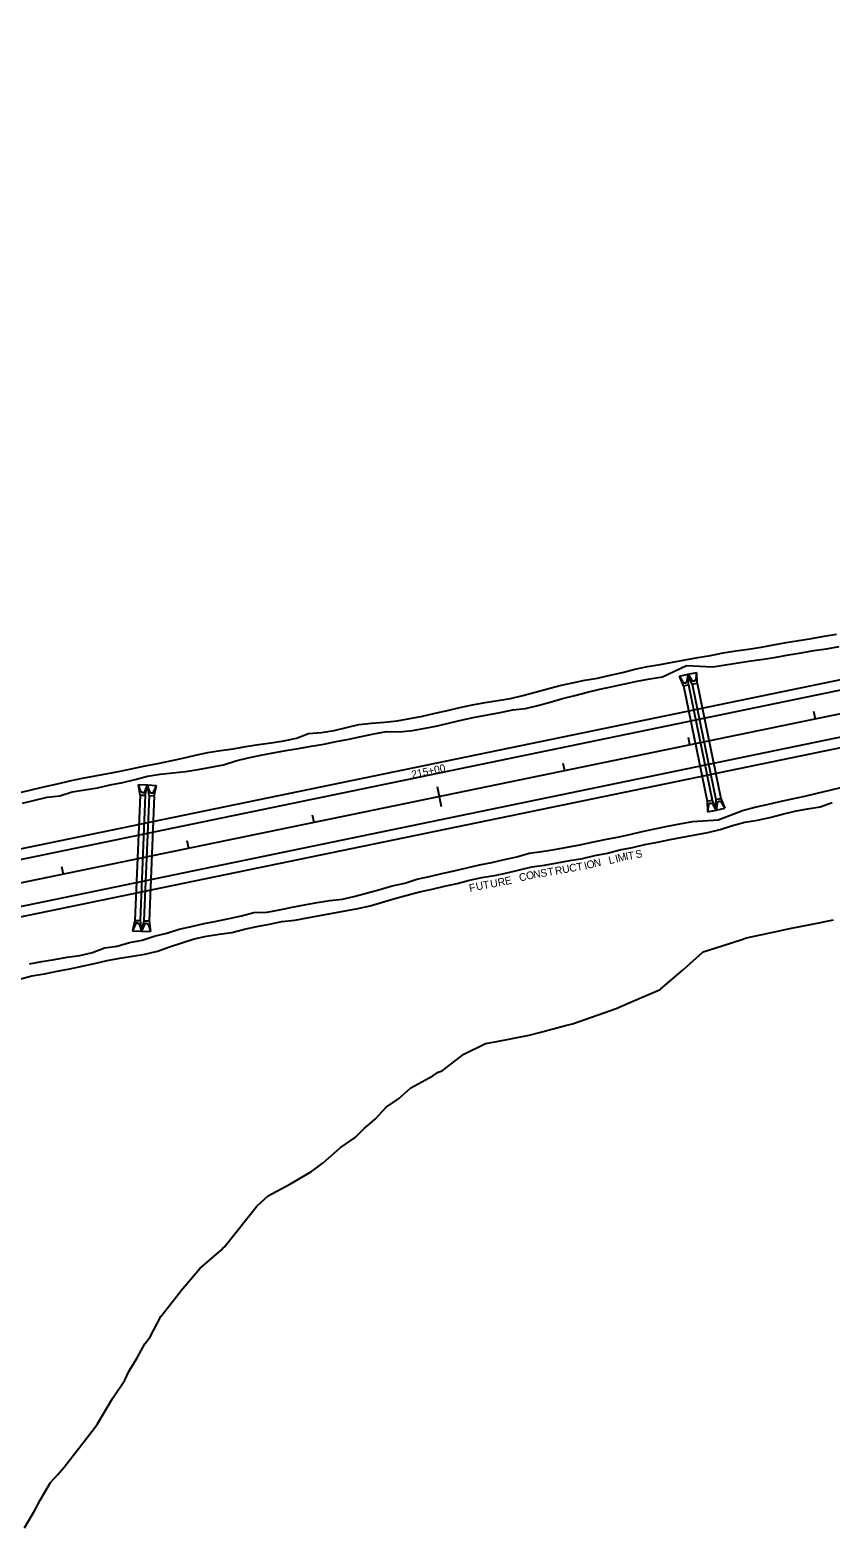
# Model space of a CAD drawing. Extents: x 979959 to 994833, y 1835619 to 1845316.
# Drawn here: x 986936 to 987562, y 1837739 to 1838917 of the extents above; entities that cross this region are included whole.
import ezdxf

# ---------------------------------------------------------------- set-up
doc = ezdxf.new("R2010")
doc.units = 0
for name, color, linetype in [('43', 7, 'Continuous'), ('Future 5 Lane Construction Limits', 7, 'Continuous'), ('R_Drainage', 7, 'Continuous'), ('R_Horz Alg', 7, 'Continuous'), ('R_Horz Alg Stationing', 7, 'Continuous'), ('R_Proposed Const Limits', 7, 'Continuous'), ('R_Proposed Road', 7, 'Continuous')]:
    doc.layers.add(name, color=color, linetype=linetype)

msp = doc.modelspace()

# ---------------------------------------------------------------- linework, layer by layer
at = {"layer": '43'}
msp.add_lwpolyline([(986932, 1837746.3), (986939.8, 1837759.8), (986944.4, 1837767.9), (986952.5, 1837781.7), (986958.2, 1837788.1), (986963, 1837793.8), (986986.5, 1837823.9), (986989.2, 1837827.8), (987000.9, 1837847.4), (987010.4, 1837861.8), (987013.6, 1837868.7), (987020.1, 1837879.2), (987020.5, 1837879.8), (987026.1, 1837890.1), (987030.2, 1837895.7), (987038.6, 1837911.6), (987052.9, 1837929.7), (987053.5, 1837930.7), (987054.5, 1837931.8), (987069, 1837949.2), (987086, 1837963.7), (987087.2, 1837965), (987088.5, 1837965.9), (987113.7, 1837997.7), (987122.5, 1838005.8), (987140, 1838015.2), (987156.5, 1838024.8), (987160.3, 1838027.8), (987165.6, 1838031.7), (987178.8, 1838043.3), (987190.4, 1838051.5), (987197.5, 1838058.6), (987206.2, 1838065.7), (987214.8, 1838075.3), (987224.5, 1838081.6), (987233.9, 1838090.2), (987251.2, 1838099.7), (987255.5, 1838102.6), (987258.4, 1838103.6), (987275.4, 1838116.6), (987292.4, 1838124.9), (987299.8, 1838126.3), (987326.4, 1838131.5), (987334.5, 1838133.6), (987355, 1838139), (987360.4, 1838140.2), (987380.5, 1838147.4), (987394.4, 1838152.2), (987405.2, 1838156.9), (987428.4, 1838166.8), (987428.8, 1838167.2), (987429.4, 1838167.6), (987447.2, 1838182.8), (987462.4, 1838196.7), (987478.1, 1838201.6), (987492, 1838206), (987496.3, 1838207.4), (987519.5, 1838212.4), (987530.3, 1838214.8), (987547.7, 1838218.2), (987564.3, 1838221.5)], dxfattribs=at)
at = {"layer": 'Future 5 Lane Construction Limits'}
for points in [[(986928.7, 1838321.1), (986938.4, 1838323.4), (986948.2, 1838325.7), (986957.9, 1838328), (986967.6, 1838330.3), (986977.4, 1838332.3), (986987.3, 1838334.2), (986997.1, 1838336), (987006.9, 1838337.8), (987016.7, 1838339.8), (987026.5, 1838341.9), (987036.3, 1838343.9), (987046.1, 1838345.9), (987055.9, 1838348), (987065.6, 1838350.2), (987075.4, 1838352.3), (987085.3, 1838353.9), (987095.2, 1838355.3), (987105.1, 1838357), (987115, 1838358.5), (987124.9, 1838360), (987134.8, 1838361.4), (987144.6, 1838363.6), (987154, 1838367.1), (987164.1, 1838368), (987174, 1838369.5), (987183.7, 1838371.9), (987193.4, 1838374.2), (987203.4, 1838375.3), (987213.4, 1838376.1), (987223.4, 1838377.1), (987233.3, 1838378.9), (987243.1, 1838380.9), (987252.9, 1838383), (987262.6, 1838385.3), (987272.3, 1838387.6), (987282.1, 1838389.6), (987292, 1838391.5), (987301.9, 1838393), (987311.8, 1838394.5), (987321.5, 1838397), (987331.2, 1838399.5), (987340.8, 1838402.2), (987350.5, 1838404.7), (987360.3, 1838406.8), (987370.1, 1838408.8), (987379.9, 1838410.5), (987389.7, 1838412.8), (987399.4, 1838414.9), (987409.1, 1838417.4), (987418.9, 1838419.5), (987428.8, 1838421.2), (987438.6, 1838422.9), (987448.5, 1838424.7), (987458.3, 1838426.5), (987468.1, 1838428.3), (987478, 1838430.3), (987487.9, 1838431.8), (987497.8, 1838433.1), (987507.7, 1838434.6), (987517.5, 1838436.6), (987527.4, 1838438.3), (987537.2, 1838439.9), (987547.1, 1838441.5), (987557, 1838443.3), (987566.8, 1838444.9)], [(986928.2, 1838175.2), (986937.9, 1838177.8), (986947.8, 1838179.3), (986957.5, 1838181.5), (986967.4, 1838183.3), (986977.2, 1838185.3), (986986.9, 1838187.4), (986996.6, 1838189.8), (987006.5, 1838191.7), (987016.4, 1838193.1), (987026.2, 1838194.8), (987036, 1838197.1), (987045.5, 1838200.4), (987055.1, 1838203.6), (987064.6, 1838206.8), (987074.4, 1838208.7), (987084.3, 1838210.3), (987094.2, 1838211.8), (987103.9, 1838214.2), (987113.7, 1838216.5), (987123.5, 1838218.2), (987133.3, 1838220.3), (987143.3, 1838221.4), (987153.1, 1838223.1), (987163, 1838224.9), (987172.8, 1838226.9), (987182.6, 1838228.7), (987192.5, 1838230.5), (987202.2, 1838232.6), (987211.9, 1838235.4), (987221.5, 1838238.3), (987231.1, 1838241), (987240.9, 1838243.4), (987250.6, 1838245.6), (987260.4, 1838247.8), (987270.1, 1838250.1), (987279.8, 1838252.5), (987289.6, 1838254.6), (987299.5, 1838256.2), (987309.2, 1838258.3), (987319, 1838260.7), (987328.7, 1838262.9), (987338.6, 1838264.4), (987348.5, 1838266.1), (987358.3, 1838268), (987368.2, 1838269.6), (987377.9, 1838272), (987387.7, 1838273.8), (987397.4, 1838276.4), (987407.3, 1838278.1), (987417, 1838280.4), (987426.8, 1838282.3), (987436.6, 1838284.4), (987446.4, 1838286.3), (987456.3, 1838288.1), (987466.1, 1838289.8), (987475.8, 1838292.2), (987485.4, 1838295.3), (987495.1, 1838297.9), (987505, 1838299.4), (987514.7, 1838301.7), (987524.4, 1838304.2), (987534.2, 1838306.4), (987544, 1838308.3), (987553.9, 1838310), (987563.4, 1838313.2)]]:
    msp.add_lwpolyline(points, dxfattribs=at)
at = {"layer": 'R_Drainage'}
for p, q in [((987443.9, 1838412.1), (987450.8, 1838413.5)), ((987447, 1838404.4), (987443.9, 1838412.1)), ((987446.6, 1838407.8), (987443.9, 1838412.1)), ((987450, 1838408.5), (987450.8, 1838413.5)), ((987450.8, 1838413.5), (987457.6, 1838415)), ((987451, 1838405.2), (987450.8, 1838413.5)), ((987453.9, 1838405.8), (987450.8, 1838413.5)), ((987453.5, 1838409.2), (987450.8, 1838413.5)), ((987456.9, 1838409.9), (987457.6, 1838415)), ((987457.8, 1838406.6), (987457.6, 1838415)), ((987447, 1838404.4), (987451, 1838405.2)), ((987447, 1838404.4), (987465.6, 1838314.3)), ((987451, 1838405.2), (987469.6, 1838315.1)), ((987453.9, 1838405.8), (987457.8, 1838406.6)), ((987453.9, 1838405.8), (987472.5, 1838315.7)), ((987457.8, 1838406.6), (987476.4, 1838316.5)), ((987021.2, 1838327.3), (987028.2, 1838327)), ((987022.4, 1838319.1), (987021.2, 1838327.3)), ((987022.8, 1838322.4), (987021.2, 1838327.3)), ((987026.3, 1838322.3), (987028.2, 1838327)), ((987026.4, 1838318.9), (987028.2, 1838327)), ((987028.2, 1838327), (987035.2, 1838326.7)), ((987029.4, 1838318.8), (987028.2, 1838327)), ((987029.8, 1838322.1), (987028.2, 1838327)), ((987033.2, 1838322), (987035.2, 1838326.7)), ((987033.4, 1838318.6), (987035.2, 1838326.7)), ((987022.4, 1838319.1), (987018.4, 1838221.2)), ((987022.4, 1838319.1), (987026.4, 1838318.9)), ((987026.4, 1838318.9), (987022.4, 1838221)), ((987029.4, 1838318.8), (987025.4, 1838220.9)), ((987029.4, 1838318.8), (987033.4, 1838318.6)), ((987033.4, 1838318.6), (987029.4, 1838220.7)), ((987465.6, 1838314.3), (987469.6, 1838315.1)), ((987465.6, 1838314.3), (987465.8, 1838306)), ((987469.6, 1838315.1), (987472.7, 1838307.4)), ((987472.5, 1838315.7), (987476.4, 1838316.5)), ((987472.5, 1838315.7), (987472.7, 1838307.4)), ((987476.4, 1838316.5), (987479.5, 1838308.9)), ((987466.6, 1838311.1), (987465.8, 1838306)), ((987465.8, 1838306), (987472.7, 1838307.4)), ((987470, 1838311.8), (987472.7, 1838307.4)), ((987473.5, 1838312.5), (987472.7, 1838307.4)), ((987472.7, 1838307.4), (987479.5, 1838308.9)), ((987476.8, 1838313.2), (987479.5, 1838308.9)), ((987018.4, 1838221.2), (987016.6, 1838213.1)), ((987018.4, 1838221.2), (987022.4, 1838221)), ((987022.4, 1838221), (987023.6, 1838212.8)), ((987025.4, 1838220.9), (987023.6, 1838212.8)), ((987025.4, 1838220.9), (987029.4, 1838220.7)), ((987029.4, 1838220.7), (987030.6, 1838212.5)), ((987018.5, 1838217.8), (987016.6, 1838213.1)), ((987016.6, 1838213.1), (987023.6, 1838212.8)), ((987022, 1838217.7), (987023.6, 1838212.8)), ((987025.5, 1838217.5), (987023.6, 1838212.8)), ((987023.6, 1838212.8), (987030.6, 1838212.5)), ((987029, 1838217.4), (987030.6, 1838212.5))]:
    msp.add_line(p, q, dxfattribs=at)
for centre, start, end in [((987448.2, 1838408.7), 211.983, 351.3459), ((987455.1, 1838410.2), 211.983, 351.3459), ((987024.6, 1838323), 197.983, 337.3459), ((987031.6, 1838322.7), 197.983, 337.3459), ((987475.3, 1838312.2), 31.9829, 171.3457), ((987468.4, 1838310.8), 31.9829, 171.3457), ((987020.2, 1838217.1), 17.9829, 157.3457), ((987027.2, 1838216.8), 17.9829, 157.3457)]:
    msp.add_arc(centre, 1.83, start, end, dxfattribs=at)
at = {"layer": 'R_Horz Alg'}
msp.add_line((984572.5, 1837764), (990033.8, 1838891.5), dxfattribs=at)
at = {"layer": 'R_Horz Alg Stationing'}
for points in [[(987548.7, 1838384.6), (987549.9, 1838378.7)], [(987450.7, 1838364.3), (987451.9, 1838358.5)], [(987352.8, 1838344.1), (987354, 1838338.3)], [(987254.5, 1838325.9), (987257.7, 1838310.2)], [(987156.9, 1838303.7), (987158.1, 1838297.8)], [(987059, 1838283.5), (987060.2, 1838277.6)], [(986961.1, 1838263.3), (986962.3, 1838257.4)]]:
    msp.add_lwpolyline(points, dxfattribs=at)
at = {"layer": 'R_Proposed Const Limits'}
for points in [[(986930.4, 1838312.7), (986940.2, 1838315), (986949.9, 1838317.5), (986959.8, 1838318.6), (986969.4, 1838321.7), (986979.3, 1838323.3), (986989.2, 1838324.8), (986999, 1838327), (987008.8, 1838328.8), (987018.5, 1838331.4), (987028.2, 1838333.9), (987038, 1838335.5), (987048, 1838336.6), (987058, 1838337.6), (987067.9, 1838339.1), (987077.8, 1838341), (987087.6, 1838342.8), (987097.2, 1838345.8), (987106.9, 1838348.3), (987116.7, 1838350.2), (987126.5, 1838352.1), (987136.3, 1838353.9), (987146.2, 1838355.6), (987156.1, 1838357.2), (987165.9, 1838358.9), (987175.7, 1838360.9), (987185.5, 1838362.9), (987195.3, 1838364.9), (987205.1, 1838366.9), (987215, 1838368.7), (987225.2, 1838368.6), (987235.2, 1838369.5), (987245.1, 1838371.3), (987254.9, 1838373.3), (987264.6, 1838375.6), (987274.4, 1838377.8), (987284.1, 1838380), (987293.9, 1838381.9), (987303.8, 1838383.6), (987313.6, 1838385.6), (987323.6, 1838386.8), (987333.3, 1838389.1), (987342.9, 1838391.8), (987352.6, 1838394.5), (987362.3, 1838397), (987372, 1838399.5), (987381.7, 1838401.8), (987391.5, 1838403.9), (987401.3, 1838406), (987411, 1838408.2), (987420.9, 1838410), (987430.8, 1838411.6), (987449.4, 1838420.3), (987470, 1838419.3), (987479.9, 1838421), (987489.8, 1838422.5), (987499.7, 1838423.9), (987509.6, 1838425.2), (987519.5, 1838427), (987529.3, 1838428.7), (987539.2, 1838430.4), (987549.1, 1838432.1), (987559, 1838433.5), (987568.8, 1838435.3)], [(986935.9, 1838187.3), (986945.7, 1838189.1), (986955.6, 1838190.6), (986965.5, 1838192.3), (986975.4, 1838193.8), (986985.1, 1838196.1), (986994.6, 1838199.7), (987004.5, 1838201), (987014.2, 1838203.9), (987024, 1838205.8), (987033.5, 1838208.9), (987043.2, 1838211.3), (987052.9, 1838214.2), (987062.6, 1838216.3), (987072.4, 1838218.6), (987082.2, 1838220.6), (987092, 1838222.6), (987101.7, 1838224.8), (987111.4, 1838227.2), (987121.6, 1838227.7), (987131.4, 1838229.5), (987141.2, 1838231.4), (987151, 1838233.3), (987160.8, 1838235.2), (987170.7, 1838236.8), (987180.7, 1838237.8), (987190.5, 1838240), (987200.2, 1838242.6), (987209.8, 1838245.4), (987219.4, 1838248.2), (987229.2, 1838250.2), (987238.8, 1838253.3), (987248.6, 1838255.5), (987258.3, 1838257.8), (987268, 1838260), (987277.8, 1838262.2), (987287.6, 1838264.5), (987297.3, 1838266.5), (987307.1, 1838268.8), (987316.9, 1838270.9), (987326.5, 1838273.8), (987336.4, 1838275.1), (987346.3, 1838276.6), (987356.2, 1838278.4), (987366, 1838280.3), (987375.8, 1838282.2), (987385.6, 1838284.3), (987395.4, 1838286.3), (987405.1, 1838288.4), (987414.9, 1838290.6), (987424.7, 1838292.6), (987434.5, 1838294.8), (987444.3, 1838296.6), (987454.1, 1838298.4), (987474.3, 1838299.8), (987493.2, 1838307), (987502.9, 1838309.7), (987512.6, 1838311.8), (987522.4, 1838314.2), (987532.1, 1838316.2), (987541.9, 1838318.3), (987551.7, 1838320.6), (987561.4, 1838323), (987571.1, 1838325.3)]]:
    msp.add_lwpolyline(points, dxfattribs=at)
at = {"layer": 'R_Proposed Road'}
for p, q in [((984567.2, 1837789.5), (990028.6, 1838916.9)), ((984568.8, 1837781.7), (990030.2, 1838909.1)), ((984576.1, 1837746.4), (990037.5, 1838873.9)), ((984577.7, 1837738.6), (990039.1, 1838866))]:
    msp.add_line(p, q, dxfattribs=at)

# ---------------------------------------------------------------- texts
at = {"layer": 'Future 5 Lane Construction Limits'}
for s, rotation, p in [('I', 14.1637, (987370.2, 1838260.8)), ('O', 14.1637, (987372.2, 1838261.3)), ('N', 10.4071, (987377.4, 1838262.8)), ('L', 14.643, (987389.4, 1838265)), ('I', 14.643, (987394.6, 1838266.3)), ('M', 14.643, (987396.5, 1838266.8)), ('I', 9.8779, (987402.3, 1838268.1)), ('T', 9.8779, (987404.2, 1838268.4)), ('S', 13.3247, (987410.3, 1838269.6)), ('E', 11.9268, (987308.1, 1838248.8)), ('C', 12.7152, (987319.3, 1838251.5)), ('O', 12.7152, (987324.8, 1838252.8)), ('N', 8.9297, (987330.1, 1838254)), ('S', 8.9297, (987335.7, 1838254.9)), ('T', 9.8667, (987341.4, 1838255.8)), ('R', 9.8667, (987347.2, 1838256.8)), ('U', 10.7295, (987352.9, 1838257.8)), ('C', 9.0651, (987358.3, 1838258.9)), ('T', 9.0651, (987363.9, 1838259.8)), ('F', 12.1232, (987280.2, 1838243.3)), ('U', 12.1232, (987285.5, 1838244.5)), ('T', 9.5672, (987290.9, 1838245.6)), ('U', 9.5672, (987296.6, 1838246.6)), ('R', 11.9268, (987302.6, 1838247.7))]:
    msp.add_text(s, height=6, rotation=rotation, dxfattribs=at).set_placement(p)
at = {"layer": 'R_Horz Alg Stationing'}
msp.add_text('215+00', height=6, rotation=11.6644, dxfattribs=at).set_placement((987235.1, 1838332.1))

doc.saveas('drawing.dxf')
